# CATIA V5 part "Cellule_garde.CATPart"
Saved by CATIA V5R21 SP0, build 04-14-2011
Part number: Cellule_garde
Bounding box of the stored display mesh (mm): x -17.5 to 17.5, y -115 to 115, z -22.303 to 17.499
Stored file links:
  C:\Users\zerma\Pictures\Stage Stomate\Cellule_garde.CATPart
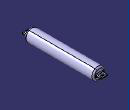
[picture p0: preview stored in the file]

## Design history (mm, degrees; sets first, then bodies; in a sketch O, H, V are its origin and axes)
Body1 (main body)
  Sketch1 on yz-plane, origin (0, 0, 0), H (0, 1, 0), V (0, 0, 1)
    line L1 (-95, -12.5) -> (95, -12.5)
    point P1 (-95, -12.5)
    line L2 (-100, -17.5) -> (100, -17.5)
    point P3 (-100, -17.5)
    line L3 (-95, -12.5) -> (-95, 0)
    point P5 (-95, 0)
    line L4 (-100, -17.5) -> (-100, 0)
    point P6 (-100, 0)
    line L5 (-95, 0) -> (-100, 0)
    point P7 (95, 0)
    point P8 (100, 0)
    line L6 (95, 0) -> (100, 0)
    point P9 (100, -17.5)
    line L7 (100, -17.5) -> (100, 0)
    point P10 (95, -12.5)
    line L8 (95, -12.5) -> (95, 0)
    distance L1 L2 = 5
    length L4 = 17.5
    distance L4 L3 = 5
    length L1 = 190
    length L2 = 200
    distance L3 V = 95
    horizontal: L1 H, L2 H, L5 H
    vertical: L3 V, L4 V
    symmetry: P5 P7 V, P6 P8 V, L5 L6 V, P3 P9 V, L4 L7 V, P1 P10 V, L3 L8 V
    coincidence: L5 H
  Shaft1: profile Sketch1, axis Sketch1.H, angle 360
  Sketch2 on face of Shaft1 from Sketch1.L4, origin (0, -100, 0), H (1, 0, 0), V (0, 0, 1)
    line L1 (-10, 2.5) -> (10, 2.5)
    line L2 (10, 2.5) -> (10, -2.5)
    line L3 (10, -2.5) -> (-10, -2.5)
    line L4 (-10, -2.5) -> (-10, 2.5)
    length L2 = 5
    length L1 = 20
    horizontal: L1 H, L3 H
    vertical: L2 V, L4 V
    symmetry: L3 L1 H, L4 L2 V
  Pad1: profile Sketch2, direction (0, -1, 0), length 15
  Sketch3 on face of Pad1 from Sketch2.L1, origin (0, 0, 2.5), H (1, 0, 0), V (0, 1, 0)
    circle A1 centre (0, -107.5) radius 2.5
    point P1 (0, -107.5)
    reference projected line E1 (10, -115) -> (-10, -115) from edge [face of Pad1 from Sketch2.L1 | end face of Pad1]
    radius A1 = 2.5
    distance P1 E1 = 7.5
    coincidence: P1 V
  Pocket1: profile Sketch3, direction (0, 0, 1), length 5, mirrored extent
  Fillet1: radius 2, on edge [face of Pad1 from Sketch2.L4 | end face of Pad1]; edge [face of Pad1 from Sketch2.L4 | face of Pad1 from Sketch2.L1]; edge [face of Pad1 from Sketch2.L1 | end face of Pad1]; edge [face of Pad1 from Sketch2.L3 | end face of Pad1]; edge [face of Pad1 from Sketch2.L2 | end face of Pad1]; edge [face of Pad1 from Sketch2.L1 | face of Pad1 from Sketch2.L2]; edge [face of Pad1 from Sketch2.L2 | face of Pad1 from Sketch2.L3]; edge [face of Pocket1 from Sketch3.A1 | face of Pad1 from Sketch2.L1]; edge [face of Shaft1 from Sketch1.L4 | face of Pad1 from Sketch2.L1]; edge [face of Shaft1 from Sketch1.L4 | face of Pad1 from Sketch2.L2]; edge [face of Shaft1 from Sketch1.L4 | face of Pad1 from Sketch2.L4]; edge [face of Pad1 from Sketch2.L3 | face of Pad1 from Sketch2.L4]; edge [face of Pocket1 from Sketch3.A1 | face of Pad1 from Sketch2.L3]; edge [face of Shaft1 from Sketch1.L4 | face of Pad1 from Sketch2.L3]
  Mirror1: of Pad1, Pocket1, Fillet1, about zx-plane
  Fillet2: radius 4, on edge [face of Shaft1 from Sketch1.L4 | face of Shaft1 from Sketch1.L2]; edge [face of Shaft1 from Sketch1.L2 | face of Shaft1 from Sketch1.L7]
  Sketch4 on yz-plane, origin (0, 0, 0), H (0, 1, 0), V (0, 0, 1)
    point P1 (-84, 0)
    line L1 (-84, 0) -> (-94, -20)
    point P3 (-80, 0)
    line L2 (-80, 0) -> (-90, -20)
    line L3 (-84, 0) -> (-80, 0)
    line L4 (-94, -20) -> (-90, -20)
    distance P1 P3 = 4
    distance V P3 = 80
    length L4 = 4
    horizontal: L3 H, L4 H
  Shaft2: profile Sketch4, axis Sketch4.L2, angle 360
  Fillet3: radius 1, on face of Shaft2 from Sketch4.L4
